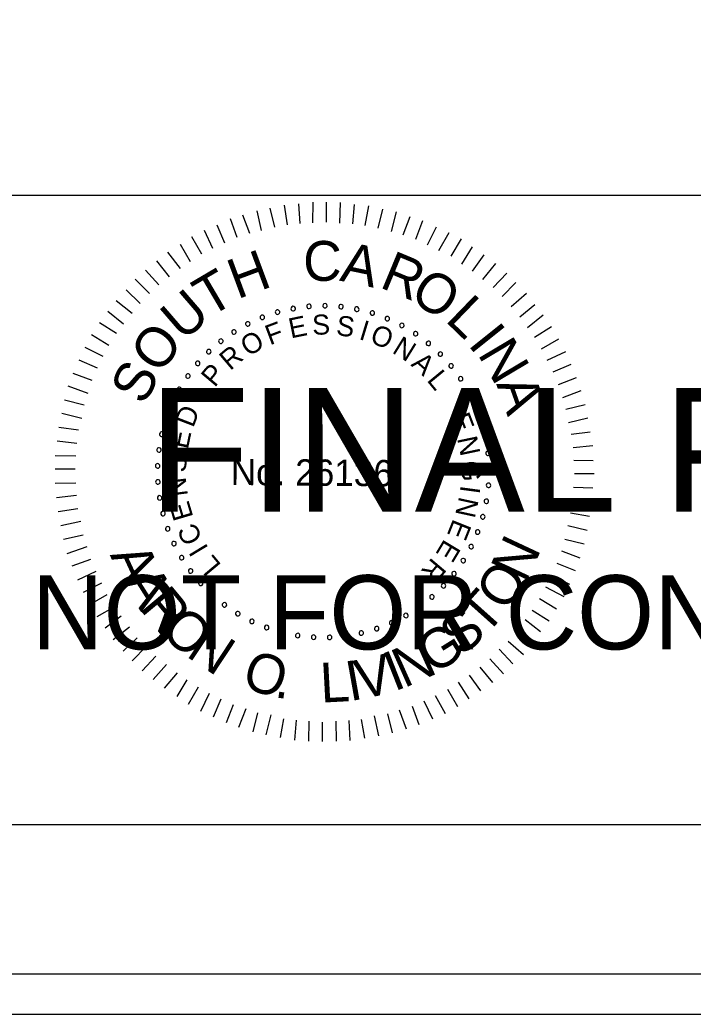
# Model space of a CAD drawing. Extents: x 967 to 1326, y 964 to 2584.
# Drawn here: x 1170.56 to 1189.3, y 1243.72 to 1271.36 of the extents above; entities that cross this region are included whole.
import ezdxf

# ---------------------------------------------------------------- set-up
doc = ezdxf.new("R2010")
doc.units = 0
for name, color, linetype in [('RD_SHT_Misc1', 7, 'Continuous'), ('RD_SHT_Misc2', 7, 'Continuous'), ('RD_XS_ExPaveRet', 7, 'Continuous'), ('RD_XS_TX_Elev_EX', 7, 'Continuous')]:
    doc.layers.add(name, color=color, linetype=linetype)

msp = doc.modelspace()

# ---------------------------------------------------------------- linework, layer by layer
at = {"layer": 'RD_SHT_Misc1'}
for p, q in [((1178.01, 1265.663), (1177.93, 1266.209)), ((1178.364, 1265.699), (1178.33, 1266.244)), ((1178.717, 1265.719), (1178.722, 1266.295)), ((1179.093, 1265.739), (1179.098, 1266.292)), ((1179.469, 1265.713), (1179.489, 1266.288)), ((1179.829, 1265.687), (1179.872, 1266.231)), ((1180.174, 1265.646), (1180.271, 1266.19)), ((1176.964, 1265.419), (1176.769, 1265.935)), ((1177.287, 1265.508), (1177.169, 1266.054)), ((1177.657, 1265.597), (1177.53, 1266.128)), ((1180.535, 1265.573), (1180.662, 1266.102)), ((1180.902, 1265.478), (1181.045, 1266.022)), ((1176.264, 1265.156), (1176.053, 1265.657)), ((1176.61, 1265.306), (1176.423, 1265.83)), ((1181.231, 1265.384), (1181.428, 1265.896)), ((1181.584, 1265.265), (1181.78, 1265.786)), ((1175.933, 1265.005), (1175.699, 1265.506)), ((1181.905, 1265.109), (1182.154, 1265.606)), ((1182.226, 1264.953), (1182.506, 1265.45)), ((1175.308, 1264.634), (1175.036, 1265.12)), ((1175.624, 1264.846), (1175.352, 1265.332)), ((1182.562, 1264.789), (1182.85, 1265.27)), ((1175.03, 1264.445), (1174.681, 1264.9)), ((1182.86, 1264.572), (1183.163, 1265.053)), ((1183.158, 1264.378), (1183.484, 1264.828)), ((1174.729, 1264.217), (1174.372, 1264.665)), ((1183.447, 1264.145), (1183.811, 1264.587)), ((1174.435, 1263.997), (1174.062, 1264.399)), ((1183.729, 1263.92), (1184.116, 1264.316)), ((1174.172, 1263.753), (1173.776, 1264.148)), ((1183.98, 1263.672), (1184.368, 1264.061)), ((1173.909, 1263.479), (1173.52, 1263.858)), ((1184.232, 1263.394), (1184.657, 1263.767)), ((1173.684, 1263.197), (1173.242, 1263.546)), ((1184.475, 1263.108), (1184.892, 1263.45)), ((1173.451, 1262.9), (1173.009, 1263.256)), ((1184.687, 1262.807), (1185.128, 1263.156)), ((1173.257, 1262.64), (1172.776, 1262.936)), ((1173.039, 1262.312), (1172.559, 1262.6)), ((1184.885, 1262.544), (1185.355, 1262.832)), ((1185.081, 1262.213), (1185.56, 1262.493)), ((1172.883, 1262.006), (1172.379, 1262.256)), ((1185.24, 1261.904), (1185.756, 1262.145)), ((1172.727, 1261.677), (1172.215, 1261.904)), ((1185.399, 1261.573), (1185.907, 1261.791)), ((1172.571, 1261.333), (1172.051, 1261.53)), ((1185.549, 1261.226), (1186.057, 1261.414)), ((1172.461, 1260.974), (1171.91, 1261.178)), ((1185.669, 1260.865), (1186.185, 1261.06)), ((1172.351, 1260.652), (1171.807, 1260.787)), ((1185.759, 1260.541), (1186.297, 1260.667)), ((1172.286, 1260.276), (1171.727, 1260.419)), ((1185.832, 1260.165), (1186.371, 1260.298)), ((1172.191, 1259.955), (1171.647, 1260.029)), ((1185.906, 1259.842), (1186.436, 1259.906)), ((1172.15, 1259.587), (1171.598, 1259.653)), ((1185.964, 1259.473), (1186.51, 1259.53)), ((1172.124, 1259.234), (1171.548, 1259.239)), ((1185.977, 1259.12), (1186.514, 1259.115)), ((1172.105, 1258.866), (1171.545, 1258.871)), ((1185.997, 1258.751), (1186.542, 1258.747)), ((1172.118, 1258.482), (1171.542, 1258.471)), ((1185.971, 1258.368), (1186.508, 1258.348)), ((1172.138, 1258.136), (1171.585, 1258.072)), ((1185.952, 1258.022), (1186.497, 1257.949)), ((1172.173, 1257.768), (1171.627, 1257.688)), ((1185.888, 1257.655), (1186.417, 1257.566)), ((1172.262, 1257.414), (1171.701, 1257.296)), ((1185.808, 1257.302), (1186.345, 1257.175)), ((1172.321, 1257.037), (1171.774, 1256.911)), ((1185.729, 1256.926), (1186.265, 1256.792)), ((1172.425, 1256.707), (1171.871, 1256.519)), ((1185.634, 1256.597), (1186.146, 1256.401)), ((1172.53, 1256.36), (1172.007, 1256.173)), ((1185.508, 1256.253), (1186.013, 1256.057)), ((1172.681, 1256.029), (1172.165, 1255.788)), ((1172.831, 1255.705), (1172.323, 1255.441)), ((1185.352, 1255.924), (1185.857, 1255.675)), ((1185.188, 1255.603), (1185.7, 1255.33)), ((1172.982, 1255.374), (1172.497, 1255.094)), ((1185.024, 1255.274), (1185.498, 1254.987)), ((1173.194, 1255.042), (1172.709, 1254.762)), ((1184.822, 1254.946), (1185.288, 1254.658)), ((1173.384, 1254.78), (1172.936, 1254.453)), ((1184.62, 1254.687), (1185.055, 1254.353)), ((1173.612, 1254.478), (1173.164, 1254.129)), ((1184.403, 1254.389), (1184.814, 1254.033)), ((1173.832, 1254.177), (1173.437, 1253.812)), ((1184.155, 1254.092), (1184.574, 1253.72)), ((1174.091, 1253.945), (1173.689, 1253.541)), ((1183.899, 1253.864), (1184.28, 1253.454)), ((1174.35, 1253.674), (1173.97, 1253.263)), ((1183.644, 1253.597), (1184.024, 1253.18)), ((1174.64, 1253.442), (1174.275, 1253.022)), ((1174.937, 1253.209), (1174.58, 1252.782)), ((1183.358, 1253.37), (1183.715, 1252.944)), ((1175.212, 1253.014), (1174.932, 1252.549)), ((1182.764, 1252.952), (1183.059, 1252.482)), ((1183.065, 1253.141), (1183.384, 1252.709)), ((1175.525, 1252.812), (1175.245, 1252.331)), ((1182.463, 1252.755), (1182.743, 1252.269)), ((1175.83, 1252.633), (1175.588, 1252.136)), ((1176.159, 1252.477), (1175.94, 1251.98)), ((1181.8, 1252.431), (1182.041, 1251.93)), ((1182.124, 1252.581), (1182.396, 1252.08)), ((1176.503, 1252.321), (1176.307, 1251.816)), ((1176.855, 1252.211), (1176.651, 1251.69)), ((1177.177, 1252.1), (1177.05, 1251.572)), ((1181.122, 1252.175), (1181.31, 1251.652)), ((1181.476, 1252.28), (1181.664, 1251.771)), ((1177.545, 1252.036), (1177.409, 1251.484)), ((1177.897, 1251.933), (1177.808, 1251.412)), ((1178.25, 1251.892), (1178.207, 1251.34)), ((1178.603, 1251.866), (1178.598, 1251.313)), ((1178.978, 1251.84), (1178.974, 1251.295)), ((1179.355, 1251.86), (1179.365, 1251.307)), ((1179.715, 1251.88), (1179.749, 1251.327)), ((1180.061, 1251.915), (1180.149, 1251.393)), ((1180.423, 1252.012), (1180.541, 1251.458)), ((1180.791, 1252.07), (1180.926, 1251.54))]:
    msp.add_line(p, q, dxfattribs=at)
for centre, start, end in [((1178.609, 1263.397), 5.0653, 185.0653), ((1179.055, 1263.414), 359.5268, 179.5268), ((1179.055, 1263.414), 179.5268, 359.5268), ((1179.5, 1263.388), 353.9884, 173.9884), ((1177.312, 1263.091), 21.6807, 201.6807), ((1177.734, 1263.235), 16.1422, 196.1422), ((1177.734, 1263.235), 196.1422, 16.1422), ((1178.168, 1263.337), 10.6038, 190.6038), ((1178.168, 1263.337), 190.6038, 10.6038), ((1178.609, 1263.397), 185.0653, 5.0653), ((1179.5, 1263.388), 173.9884, 353.9884), ((1179.94, 1263.319), 168.4499, 348.4499), ((1179.94, 1263.319), 348.4499, 168.4499), ((1180.372, 1263.208), 162.9114, 342.9114), ((1180.372, 1263.208), 342.9114, 162.9114), ((1176.906, 1262.908), 27.2191, 207.2191), ((1176.906, 1262.908), 207.2191, 27.2191), ((1177.312, 1263.091), 201.6807, 21.6807), ((1180.79, 1263.056), 157.373, 337.373), ((1180.79, 1263.056), 337.373, 157.373), ((1181.193, 1262.864), 151.8345, 331.8345), ((1181.193, 1262.864), 331.8345, 151.8345), ((1176.52, 1262.686), 32.7576, 212.7576), ((1176.52, 1262.686), 212.7576, 32.7576), ((1181.574, 1262.634), 146.2961, 326.2961), ((1181.574, 1262.634), 326.2961, 146.2961), ((1176.156, 1262.428), 38.2961, 218.2961), ((1176.156, 1262.428), 218.2961, 38.2961), ((1181.932, 1262.368), 140.7576, 320.7576), ((1181.932, 1262.368), 320.7576, 140.7576), ((1175.82, 1262.135), 43.8345, 223.8345), ((1175.82, 1262.135), 223.8345, 43.8345), ((1182.263, 1262.069), 135.2191, 315.2191), ((1182.263, 1262.069), 315.2191, 135.2191), ((1175.513, 1261.812), 49.373, 229.373), ((1175.513, 1261.812), 229.373, 49.373), ((1182.563, 1261.74), 129.6807, 309.6807), ((1182.563, 1261.74), 309.6807, 129.6807), ((1175.239, 1261.461), 54.9114, 234.9114), ((1175.239, 1261.461), 234.9114, 54.9114), ((1182.83, 1261.383), 124.1422, 304.1422), ((1182.83, 1261.383), 304.1422, 124.1422), ((1175, 1261.085), 60.4499, 240.4499), ((1175, 1261.085), 240.4499, 60.4499), ((1183.061, 1261.002), 118.6038, 298.6038), ((1183.061, 1261.002), 298.6038, 118.6038), ((1174.798, 1260.687), 65.9884, 245.9884), ((1174.798, 1260.687), 245.9884, 65.9884), ((1183.255, 1260.601), 113.0653, 293.0653), ((1183.255, 1260.601), 293.0653, 113.0653), ((1174.636, 1260.272), 71.5268, 251.5268), ((1174.636, 1260.272), 251.5268, 71.5268), ((1183.408, 1260.182), 107.5268, 287.5268), ((1183.408, 1260.182), 287.5268, 107.5268), ((1174.514, 1259.843), 77.0653, 257.0653), ((1174.514, 1259.843), 257.0653, 77.0653), ((1183.521, 1259.751), 101.9884, 281.9884), ((1183.521, 1259.751), 281.9884, 101.9884), ((1174.435, 1259.405), 82.6038, 262.6038), ((1174.435, 1259.405), 262.6038, 82.6038), ((1183.592, 1259.311), 96.4499, 276.4499), ((1183.592, 1259.311), 276.4499, 96.4499), ((1174.398, 1258.961), 88.1422, 268.1422), ((1174.398, 1258.961), 268.1422, 88.1422), ((1183.619, 1258.866), 90.9114, 270.9114), ((1183.619, 1258.866), 270.9114, 90.9114), ((1174.404, 1258.515), 93.6807, 273.6807), ((1174.404, 1258.515), 273.6807, 93.6807), ((1183.604, 1258.421), 85.373, 265.373), ((1183.604, 1258.421), 265.373, 85.373), ((1174.453, 1258.072), 99.2191, 279.2191), ((1174.453, 1258.072), 279.2191, 99.2191), ((1183.546, 1257.979), 79.8345, 259.8345), ((1183.546, 1257.979), 259.8345, 79.8345), ((1174.545, 1257.636), 104.7576, 284.7576), ((1174.545, 1257.636), 284.7576, 104.7576), ((1183.445, 1257.545), 74.2961, 254.2961), ((1183.445, 1257.545), 254.2961, 74.2961), ((1174.678, 1257.211), 110.2961, 290.2961), ((1174.678, 1257.211), 290.2961, 110.2961), ((1183.303, 1257.122), 68.7576, 248.7576), ((1183.303, 1257.122), 248.7576, 68.7576), ((1174.852, 1256.8), 115.8345, 295.8345), ((1174.852, 1256.8), 295.8345, 115.8345), ((1183.121, 1256.716), 63.2191, 243.2191), ((1183.121, 1256.716), 243.2191, 63.2191), ((1175.065, 1256.409), 121.373, 301.373), ((1175.065, 1256.409), 301.373, 121.373), ((1182.9, 1256.328), 57.6807, 237.6807), ((1182.9, 1256.328), 237.6807, 57.6807), ((1175.314, 1256.039), 126.9114, 306.9114), ((1175.314, 1256.039), 306.9114, 126.9114), ((1182.643, 1255.964), 52.1422, 232.1422), ((1182.643, 1255.964), 232.1422, 52.1422), ((1175.598, 1255.696), 132.4499, 312.4499), ((1175.598, 1255.696), 312.4499, 132.4499), ((1182.353, 1255.627), 46.6038, 226.6038), ((1175.914, 1255.381), 137.9884, 317.9884), ((1175.914, 1255.381), 317.9884, 137.9884), ((1182.353, 1255.627), 226.6038, 46.6038), ((1176.258, 1255.099), 143.5268, 323.5268), ((1176.258, 1255.099), 323.5268, 143.5268), ((1182.03, 1255.319), 41.0653, 221.0653), ((1182.03, 1255.319), 221.0653, 41.0653), ((1176.629, 1254.851), 149.0653, 329.0653), ((1176.629, 1254.851), 329.0653, 149.0653), ((1181.305, 1254.803), 29.9884, 209.9884), ((1181.68, 1255.043), 35.5268, 215.5268), ((1181.68, 1255.043), 215.5268, 35.5268), ((1177.021, 1254.639), 154.6038, 334.6038), ((1177.021, 1254.639), 334.6038, 154.6038), ((1180.908, 1254.6), 24.4499, 204.4499), ((1180.908, 1254.6), 204.4499, 24.4499), ((1181.305, 1254.803), 209.9884, 29.9884), ((1177.432, 1254.467), 160.1422, 340.1422), ((1177.432, 1254.467), 340.1422, 160.1422), ((1177.858, 1254.335), 165.6807, 345.6807), ((1177.858, 1254.335), 345.6807, 165.6807), ((1178.294, 1254.245), 351.2191, 171.2191), ((1179.627, 1254.232), 7.8345, 187.8345), ((1180.065, 1254.313), 13.373, 193.373), ((1180.065, 1254.313), 193.373, 13.373), ((1180.494, 1254.436), 18.9114, 198.9114), ((1180.494, 1254.436), 198.9114, 18.9114), ((1178.294, 1254.245), 171.2191, 351.2191), ((1178.737, 1254.198), 356.7576, 176.7576), ((1178.737, 1254.198), 176.7576, 356.7576), ((1179.183, 1254.193), 2.2961, 182.2961), ((1179.183, 1254.193), 182.2961, 2.2961), ((1179.627, 1254.232), 187.8345, 7.8345)]:
    msp.add_arc(centre, 0.0627, start, end, dxfattribs=at)
at = {"layer": 'RD_XS_ExPaveRet'}
for points in [[(967.409, 1243.72), (1326.285, 1243.72), (1326.285, 1463.72), (967.409, 1463.72)], [(988.525, 1244.84), (1326.285, 1244.84), (1326.285, 1462.6), (988.525, 1462.6)]]:
    msp.add_lwpolyline(points, close=True, dxfattribs=at)
at = {"layer": 'RD_XS_TX_Elev_EX'}
for p, q in [((996.114, 1266.486), (1323.886, 1266.486)), ((1323.886, 1248.983), (996.114, 1248.983))]:
    msp.add_line(p, q, dxfattribs=at)

# ---------------------------------------------------------------- texts
at = {"layer": 'RD_SHT_Misc1'}
for s, height, rotation, p in [('C', 1.11, 359.5482, (1178.442, 1264.108)), ('A', 1.11, 348.1981, (1179.439, 1264.115)), ('H', 1.11, 20.3637, (1176.614, 1263.587)), ('R', 1.11, 337.4344, (1180.541, 1263.937)), ('T', 1.11, 30.4992, (1175.828, 1263.072)), ('O', 1.108, 326.5869, (1181.366, 1263.609)), ('U', 1.11, 40.8022, (1175.102, 1262.403)), ('L', 1.11, 315.9488, (1182.373, 1263.003)), ('E', 0.557, 11.4103, (1178.103, 1262.503)), ('S', 0.557, 2.208, (1178.709, 1262.601)), ('S', 0.557, 352.6608, (1179.346, 1262.599)), ('F', 0.557, 20.6127, (1177.52, 1262.309)), ('I', 0.557, 343.1136, (1179.975, 1262.491)), ('O', 0.557, 338.4392, (1180.274, 1262.401)), ('I', 1.11, 308.6613, (1183.011, 1262.338)), ('O', 1.11, 52.0267, (1174.435, 1261.474)), ('O', 0.557, 30.8477, (1176.917, 1261.987)), ('N', 0.557, 328.2042, (1180.896, 1262.12)), ('N', 1.11, 300.7037, (1183.285, 1262.075)), ('R', 0.557, 40.3949, (1176.415, 1261.594)), ('A', 0.557, 318.657, (1181.424, 1261.762)), ('S', 1.108, 63.2511, (1174.029, 1260.619)), ('P', 0.557, 49.9421, (1175.985, 1261.124)), ('L', 0.557, 309.4546, (1181.869, 1261.339)), ('A', 1.11, 289.4792, (1183.814, 1261.243)), ('D', 0.557, 69.0364, (1175.386, 1260.003)), ('E', 0.557, 291.049, (1182.53, 1260.307)), ('E', 0.557, 78.2388, (1175.238, 1259.407)), ('N', 0.557, 281.8466, (1182.728, 1259.726)), ('S', 0.557, 87.786, (1175.187, 1258.772)), ('No. 26136', 0.7311, 359.5268, (1176.429, 1258.43)), ('G', 0.557, 272.2995, (1182.833, 1259.097)), ('N', 0.557, 97.3332, (1175.242, 1258.137)), ('I', 0.557, 262.4084, (1182.83, 1258.437)), ('E', 0.557, 106.5355, (1175.394, 1257.541)), ('N', 0.557, 257.7339, (1182.789, 1258.127)), ('C', 0.557, 116.4266, (1175.661, 1256.938)), ('E', 0.557, 248.1867, (1182.628, 1257.511)), ('I', 0.557, 121.1011, (1175.823, 1256.67)), ('E', 0.557, 238.9844, (1182.378, 1256.949)), ('N', 1.105, 64.8922, (1184.632, 1255.684)), ('A', 1.105, 294.7297, (1173.062, 1256.486)), ('L', 0.557, 129.9595, (1176.187, 1256.204)), ('R', 0.557, 229.782, (1182.041, 1256.435)), ('A', 1.105, 302.2892, (1173.414, 1255.72)), ('O', 1.105, 56.2059, (1184.102, 1254.874)), ('R', 1.105, 309.8487, (1173.865, 1255.007)), ('T', 1.105, 48.2685, (1183.515, 1254.211)), ('O', 1.105, 317.7861, (1174.434, 1254.33)), ('S', 1.105, 40.3311, (1182.842, 1253.636)), ('N', 1.105, 326.4725, (1175.158, 1253.686)), ('G', 1.105, 32.0198, (1182.059, 1253.14)), ('N', 1.105, 24.0824, (1181.252, 1252.776)), ('O', 1.105, 342.3472, (1176.697, 1252.82)), ('V', 1.105, 12.7741, (1180.033, 1252.457)), ('I', 1.105, 21.4605, (1180.976, 1252.681)), ('L', 1.105, 2.9677, (1178.943, 1252.379)), ('I', 1.105, 10.1523, (1179.743, 1252.418)), ('.', 1.105, 351.0336, (1177.623, 1252.536))]:
    msp.add_text(s, height=height, rotation=rotation, dxfattribs=at).set_placement(p)
at = {"layer": 'RD_SHT_Misc2'}
for s, height, p in [('FINAL PLANS', 3.4375, (1174.145, 1257.685)), ('NOT FOR CONSTRUCTION', 2.0625, (1170.901, 1253.86))]:
    msp.add_text(s, height=height, dxfattribs=at).set_placement(p)

doc.saveas('drawing.dxf')
